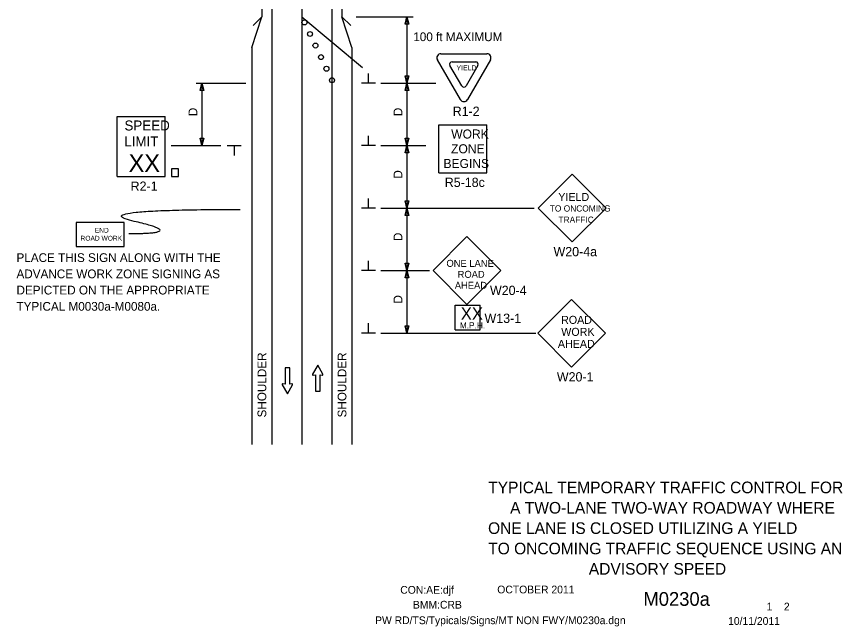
# Model space of a CAD drawing. Extents: x 16768 to 18475, y 7218 to 8259.
# Drawn here: x 16784 to 17444, y 7218 to 7706 of the extents above; entities that cross this region are included whole.
import ezdxf

# ---------------------------------------------------------------- set-up
doc = ezdxf.new("R2010")
doc.units = 0
for name, color, linetype in [('BORDER', 7, 'Continuous'), ('BORDER_SIGNAL_WO', 7, 'Continuous'), ('MT_SCRATCH_LEVEL_E', 7, 'Continuous'), ('PAVT_EDGE_EX', 7, 'Continuous'), ('TRAFFIC_SIGNS_PR', 7, 'Continuous'), ('TYPICAL_TEXT_DIMEN_PR', 7, 'Continuous')]:
    doc.layers.add(name, color=color, linetype=linetype)

msp = doc.modelspace()

# ---------------------------------------------------------------- linework, layer by layer
at = {"layer": 'MT_SCRATCH_LEVEL_E'}
for p, q in [((17024.66, 7427.22), (17020.55, 7419.98)), ((17024.66, 7427.22), (17020.55, 7419.98)), ((17028.81, 7419.98), (17024.66, 7427.22)), ((17028.81, 7419.98), (17024.66, 7427.22)), ((17002.27, 7425.26), (16998.52, 7425.26)), ((16998.52, 7425.26), (16998.52, 7412.01)), ((17002.27, 7425.26), (16998.52, 7425.26)), ((16998.52, 7425.26), (16998.52, 7412.01)), ((17002.27, 7412.01), (17002.27, 7425.26)), ((17002.27, 7412.01), (17002.27, 7425.26)), ((17021.03, 7419.29), (17022.81, 7419.61)), ((17021.03, 7419.29), (17022.81, 7419.61)), ((17022.81, 7419.61), (17022.81, 7406.35)), ((17022.81, 7419.61), (17022.81, 7406.35)), ((17026.55, 7406.35), (17026.55, 7419.61)), ((17026.55, 7419.61), (17028.33, 7419.29)), ((17026.55, 7406.35), (17026.55, 7419.61)), ((17026.55, 7419.61), (17028.33, 7419.29)), ((16996.27, 7411.64), (17000.41, 7404.4)), ((16996.27, 7411.64), (17000.41, 7404.4)), ((16998.52, 7412.01), (16996.75, 7412.32)), ((16998.52, 7412.01), (16996.75, 7412.32)), ((17000.41, 7404.4), (17004.53, 7411.64)), ((17000.41, 7404.4), (17004.53, 7411.64)), ((17004.04, 7412.32), (17002.27, 7412.01)), ((17004.04, 7412.32), (17002.27, 7412.01)), ((17022.81, 7406.35), (17026.55, 7406.35)), ((17022.81, 7406.35), (17026.55, 7406.35))]:
    msp.add_line(p, q, dxfattribs=at)
for centre, start, end in [((17020.95, 7419.75), 150.42484, 279.96381), ((17020.95, 7419.75), 150.42484, 279.96381), ((17028.4, 7419.75), 260.03619, 29.77312), ((17028.4, 7419.75), 260.03619, 29.77312), ((16996.68, 7411.86), 80.03619, 209.77312), ((16996.68, 7411.86), 80.03619, 209.77312), ((17004.12, 7411.86), 330.42484, 99.96381), ((17004.12, 7411.86), 330.42484, 99.96381)]:
    msp.add_arc(centre, 0.463, start, end, dxfattribs=at)
at = {"layer": 'PAVT_EDGE_EX'}
for p, q in [((16988.07, 8185.68), (16988.07, 7363.75)), ((17012.07, 8185.68), (17012.07, 7363.75)), ((17036.07, 8185.68), (17036.07, 7363.75)), ((16980.07, 7837.6), (16980.07, 7706.21)), ((17012.07, 7837.6), (17012.07, 7706.21)), ((17044.07, 7837.6), (17044.07, 7706.21)), ((16972.07, 7681.51), (16980.07, 7706.21)), ((16980.07, 7706.21), (16973, 7699.14)), ((17012.07, 7706.21), (17060.48, 7665.59)), ((17044.07, 7706.21), (17051.14, 7699.14)), ((17052.07, 7681.51), (17044.07, 7706.21)), ((16972.07, 7681.51), (16972.07, 7363.75)), ((17052.07, 7681.51), (17052.07, 7363.75))]:
    msp.add_line(p, q, dxfattribs=at)
for points in [[(17012.07, 7685.68), (17012.07, 7660.68)], [(17012.07, 7585.68), (17012.07, 7560.68)], [(17012.07, 7485.68), (17012.07, 7460.68)], [(17012.07, 7385.68), (17012.07, 7363.75)]]:
    msp.add_lwpolyline(points, dxfattribs=at)
at = {"layer": 'TRAFFIC_SIGNS_PR'}
for p, q in [((17138.83, 7639.83), (17120.38, 7671.79)), ((17123.15, 7676.59), (17160.07, 7676.59)), ((17162.84, 7671.8), (17144.38, 7639.83)), ((17139.92, 7650.75), (17130.47, 7667.12)), ((17132.2, 7670.12), (17151.1, 7670.12)), ((17152.83, 7667.12), (17143.38, 7650.75)), ((16864.3, 7626.26), (16902.7, 7626.26)), ((16864.3, 7578.26), (16864.3, 7626.26)), ((16902.7, 7578.26), (16902.7, 7626.26)), ((17121.46, 7581.33), (17121.46, 7619.73)), ((17121.46, 7619.73), (17159.86, 7619.73)), ((17159.86, 7581.33), (17159.86, 7619.73)), ((17121.46, 7581.33), (17159.86, 7581.33)), ((17228.15, 7580.19), (17201, 7553.04)), ((17255.3, 7553.04), (17228.15, 7580.19)), ((16864.3, 7578.26), (16902.7, 7578.26)), ((17201, 7553.04), (17228.15, 7525.88)), ((17228.15, 7525.88), (17255.3, 7553.04)), ((17144.03, 7530.26), (17116.88, 7503.11)), ((17171.19, 7503.11), (17144.03, 7530.26)), ((17116.88, 7503.11), (17144.03, 7475.96)), ((17144.03, 7475.96), (17171.19, 7503.11)), ((17227.8, 7479.95), (17200.65, 7452.8)), ((17254.95, 7452.8), (17227.8, 7479.95)), ((17134.72, 7475.4), (17154.57, 7475.4)), ((17134.72, 7455.55), (17134.72, 7475.4)), ((17154.57, 7455.55), (17154.57, 7475.4)), ((17134.72, 7455.55), (17154.57, 7455.55)), ((17200.65, 7452.8), (17227.8, 7425.65)), ((17227.8, 7425.65), (17254.95, 7452.8))]:
    msp.add_line(p, q, dxfattribs=at)
for points in [[(16907.71, 7578.26), (16913.31, 7578.26), (16913.31, 7584.43), (16907.71, 7584.43)], [(16831.33, 7522.23), (16869.73, 7522.23), (16869.73, 7541.43), (16831.33, 7541.43)]]:
    msp.add_lwpolyline(points, close=True, dxfattribs=at)
for centre in [(17014.07, 7701.63), (17018.47, 7692.37), (17022.87, 7683.1), (17027.27, 7673.84), (17031.67, 7664.57), (17036.07, 7655.31)]:
    msp.add_circle(centre, 2, dxfattribs=at)
for centre, radius, start, end in [((17123.15, 7673.39), 3.2, 90, 209.99924), ((17117.61, 7670.19), 3.2, 29.99562, 29.99924), ((17160.07, 7673.39), 3.2, 330.11476, 90), ((17132.2, 7668.12), 2, 90, 210.00073), ((17151.1, 7668.12), 2, 329.99927, 90), ((17141.65, 7651.75), 2, 210.00073, 329.99927), ((17141.61, 7641.42), 3.2, 209.99562, 211.51401), ((17141.61, 7641.43), 3.2, 211.51401, 330.00085), ((17147.15, 7638.23), 3.2, 149.99998, 150.00086)]:
    msp.add_arc(centre, radius, start, end, dxfattribs=at)
msp.add_open_spline([(16873.64, 7532.59), (16920.88, 7532.59), (16835.86, 7551.93), (16962.53, 7551.93)], degree=2, dxfattribs=at)
at = {"layer": 'TYPICAL_TEXT_DIMEN_PR'}
for p, q in [((17055.37, 7706.21), (17101.07, 7706.21)), ((17094.5, 7700.35), (17096.07, 7706.21)), ((17096.07, 7706.21), (17096.07, 7653.01)), ((17096.07, 7706.21), (17097.64, 7700.35)), ((17096.07, 7700.35), (17094.5, 7700.35)), ((17097.64, 7700.35), (17096.07, 7700.35)), ((17065.19, 7653.01), (17065.19, 7660.8)), ((17096.07, 7653.01), (17094.5, 7658.88)), ((17094.5, 7658.88), (17096.07, 7658.88)), ((17096.07, 7658.88), (17097.64, 7658.88)), ((17097.64, 7658.88), (17096.07, 7653.01)), ((16927.3, 7653.01), (16967.03, 7653.01)), ((16930.5, 7647.15), (16932.07, 7653.01)), ((16932.07, 7653.01), (16932.07, 7603.01)), ((16932.07, 7653.01), (16933.64, 7647.15)), ((17070.82, 7653.01), (17059.57, 7653.01)), ((17075.07, 7653.01), (17119.17, 7653.01)), ((17094.5, 7647.15), (17096.07, 7653.01)), ((17096.07, 7653.01), (17096.07, 7603.01)), ((17096.07, 7653.01), (17097.64, 7647.15)), ((16932.07, 7647.15), (16930.5, 7647.15)), ((16933.64, 7647.15), (16932.07, 7647.15)), ((17096.07, 7647.15), (17094.5, 7647.15)), ((17097.64, 7647.15), (17096.07, 7647.15)), ((16932.07, 7603.01), (16930.5, 7608.88)), ((16930.5, 7608.88), (16932.07, 7608.88)), ((16932.07, 7608.88), (16933.64, 7608.88)), ((16933.64, 7608.88), (16932.07, 7603.01)), ((17065.19, 7603.01), (17065.19, 7610.8)), ((17096.07, 7603.01), (17094.5, 7608.88)), ((17094.5, 7608.88), (17096.07, 7608.88)), ((17096.07, 7608.88), (17097.64, 7608.88)), ((17097.64, 7608.88), (17096.07, 7603.01)), ((16907.47, 7603.01), (16947.14, 7603.01)), ((16952.2, 7603.01), (16963.45, 7603.01)), ((16957.82, 7603.01), (16957.82, 7595.23)), ((17070.82, 7603.01), (17059.57, 7603.01)), ((17075.07, 7603.01), (17111.25, 7603.01)), ((17094.5, 7597.15), (17096.07, 7603.01)), ((17094.5, 7597.15), (17096.07, 7603.01)), ((17096.07, 7603.01), (17096.07, 7553.01)), ((17096.07, 7603.01), (17097.64, 7597.15)), ((17096.07, 7603.01), (17097.64, 7597.15)), ((17096.07, 7597.15), (17094.5, 7597.15)), ((17096.07, 7597.15), (17094.5, 7597.15)), ((17097.64, 7597.15), (17096.07, 7597.15)), ((17097.64, 7597.15), (17096.07, 7597.15)), ((17065.19, 7553.01), (17065.19, 7560.8)), ((17070.82, 7553.01), (17059.57, 7553.01)), ((17075.07, 7553.01), (17197.85, 7553.01)), ((17096.07, 7553.01), (17094.5, 7558.88)), ((17094.5, 7558.88), (17096.07, 7558.88)), ((17096.07, 7553.01), (17094.5, 7558.88)), ((17094.5, 7558.88), (17096.07, 7558.88)), ((17094.5, 7547.15), (17096.07, 7553.01)), ((17094.5, 7547.15), (17096.07, 7553.01)), ((17096.07, 7558.88), (17097.64, 7558.88)), ((17097.64, 7558.88), (17096.07, 7553.01)), ((17096.07, 7558.88), (17097.64, 7558.88)), ((17097.64, 7558.88), (17096.07, 7553.01)), ((17096.07, 7553.01), (17096.07, 7503.01)), ((17096.07, 7553.01), (17097.64, 7547.15)), ((17096.07, 7553.01), (17097.64, 7547.15)), ((17096.07, 7547.15), (17094.5, 7547.15)), ((17096.07, 7547.15), (17094.5, 7547.15)), ((17097.64, 7547.15), (17096.07, 7547.15)), ((17097.64, 7547.15), (17096.07, 7547.15)), ((17065.19, 7503.01), (17065.19, 7510.8)), ((17096.07, 7503.01), (17094.5, 7508.88)), ((17094.5, 7508.88), (17096.07, 7508.88)), ((17096.07, 7508.88), (17097.64, 7508.88)), ((17097.64, 7508.88), (17096.07, 7503.01)), ((17070.82, 7503.01), (17059.57, 7503.01)), ((17075.07, 7503.01), (17114.07, 7503.01)), ((17094.5, 7497.15), (17096.07, 7503.01)), ((17096.07, 7503.01), (17096.07, 7453.01)), ((17096.07, 7503.01), (17097.64, 7497.15)), ((17096.07, 7497.15), (17094.5, 7497.15)), ((17097.64, 7497.15), (17096.07, 7497.15)), ((17065.19, 7453.01), (17065.19, 7460.8)), ((17096.07, 7453.01), (17094.5, 7458.88)), ((17094.5, 7458.88), (17096.07, 7458.88)), ((17096.07, 7458.88), (17097.64, 7458.88)), ((17097.64, 7458.88), (17096.07, 7453.01)), ((17070.82, 7453.01), (17059.57, 7453.01)), ((17075.07, 7453.01), (17199.21, 7453.01))]:
    msp.add_line(p, q, dxfattribs=at)

# ---------------------------------------------------------------- texts
at = {"layer": 'BORDER'}
for s, p in [('TYPICAL TEMPORARY TRAFFIC CONTROL FOR', (17161.04, 7324.76)), ('A TWO-LANE TWO-WAY ROADWAY WHERE', (17178.56, 7308.46)), ('ONE LANE IS CLOSED UTILIZING A YIELD ', (17160.92, 7292.16)), ('TO ONCOMING TRAFFIC SEQUENCE USING AN', (17161.04, 7275.86)), ('ADVISORY SPEED', (17241.52, 7259.56))]:
    msp.add_text(s, height=9.3, dxfattribs=at).set_placement(p)
at = {"layer": 'BORDER_SIGNAL_WO'}
for s, height, p in [('CON:AE:djf', 6.2, (17090.69, 7244.31)), ('    OCTOBER 2011    ', 6.2, (17159.08, 7244.59)), ('    M0230a    ', 11, (17268.86, 7234.63)), ('BMM:CRB   ', 6.2, (17100.81, 7232.42)), (' 1    2 ', 6.2, (17381.45, 7230.95)), ('PW RD/TS/Typicals/Signs/MT NON FWY/M0230a.dgn     ', 6.2, (17070.55, 7219.96)), ('10/11/2011    ', 6.2, (17352.93, 7219.38))]:
    msp.add_text(s, height=height, dxfattribs=at).set_placement(p)
at = {"layer": 'TRAFFIC_SIGNS_PR'}
for s, height, p in [('YIELD', 4, (17135.68, 7663.27)), ('R1-2', 7.44, (17132.6, 7626.78)), ('SPEED', 8, (16870.06, 7615.12)), ('WORK', 7.217, (17131.46, 7608.7)), ('LIMIT', 8, (16869.9, 7602.32)), ('ZONE', 7.217, (17131.34, 7596.89)), ('XX', 14.031, (16873.41, 7582.01)), ('BEGINS', 7.217, (17125.27, 7585.08)), ('R2-1', 7.44, (16874.97, 7566.82)), ('R5-18c', 7.44, (17126.27, 7569.89)), ('YIELD', 6.4, (17217.09, 7558.71)), ('TO ONCOMING', 5, (17210.29, 7550.23)), ('TRAFFIC', 5, (17217.26, 7541.23)), ('END', 3.831, (16846.33, 7533.36)), ('ROAD WORK', 3.831, (16834.94, 7526.97)), ('W20-4a', 7.44, (17213.29, 7514.44)), ('PLACE THIS SIGN ALONG WITH THE', 7, (16783.68, 7509.85)), ('ONE LANE', 5.6, (17127.62, 7505.98)), ('ADVANCE WORK ZONE SIGNING AS', 7, (16783.68, 7496.85)), ('ROAD', 5.6, (17136.57, 7497.18)), ('AHEAD', 5.6, (17134.33, 7488.38)), ('DEPICTED ON THE APPROPRIATE', 7, (16783.68, 7483.85)), ('W20-4', 7.44, (17162.46, 7483.42)), ('TYPICAL M0030a-M0080a.', 7, (16783.68, 7470.85)), ('XX', 9.925, (17139.12, 7463.61)), ('W13-1', 7.44, (17158.1, 7461.09)), ('ROAD', 6.4, (17219.34, 7460.34)), ('M.P.H.', 4.961, (17138.34, 7456.65)), ('WORK', 6.4, (17219.45, 7450.74)), ('AHEAD', 6.4, (17216.76, 7441.14)), ('W20-1', 7.44, (17215.97, 7414.21))]:
    msp.add_text(s, height=height, dxfattribs=at).set_placement(p)
at = {"layer": 'TYPICAL_TEXT_DIMEN_PR'}
msp.add_text('100 ft MAXIMUM', height=7, dxfattribs=at).set_placement((17101.11, 7686.65))
for s, p in [('D', (16928.32, 7626.59)), ('D', (17092.32, 7626.59)), ('D', (17092.32, 7576.59)), ('D', (17092.32, 7526.59)), ('D', (17092.32, 7476.59)), ('SHOULDER', (16983.49, 7385.43)), ('SHOULDER', (17047.6, 7385.43))]:
    msp.add_text(s, height=7, rotation=90, dxfattribs=at).set_placement(p)

doc.saveas('drawing.dxf')
